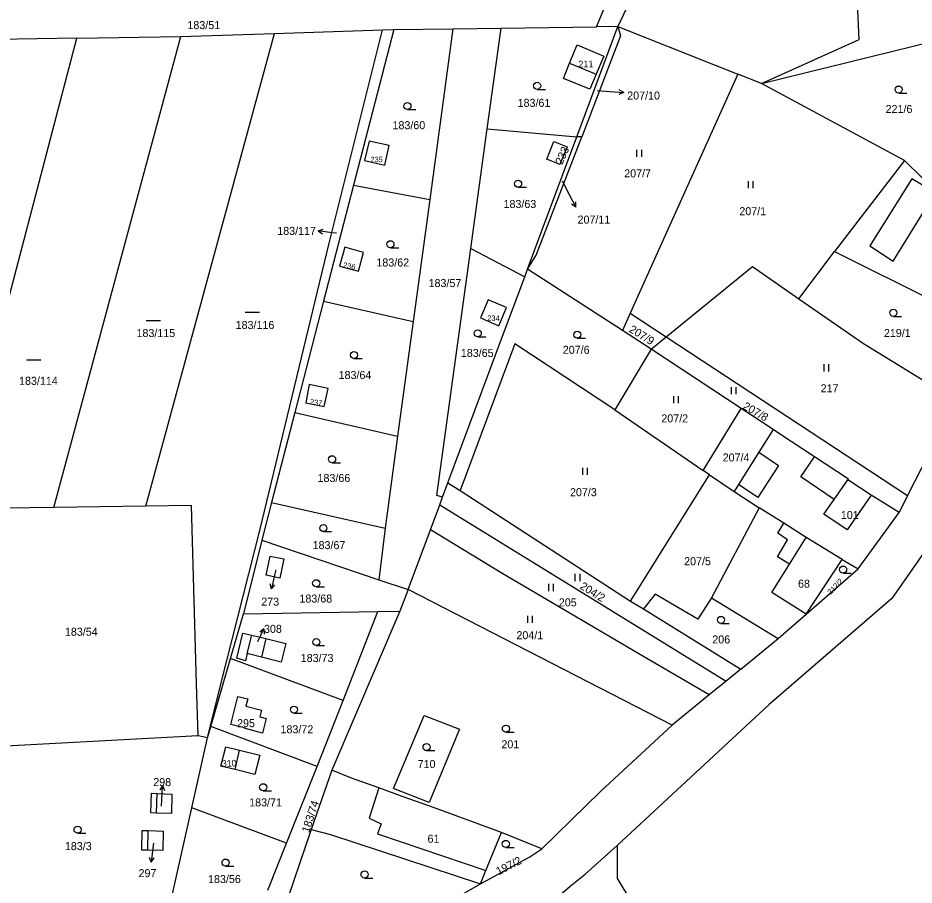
# Model space of a CAD drawing. Extents: x -747333 to -743907, y -1134120 to -1130051.
# Drawn here: x -746832.8 to -746642.5, y -1132263.2 to -1132079.1 of the extents above; entities that cross this region are included whole.
import ezdxf

# ---------------------------------------------------------------- set-up
doc = ezdxf.new("R2010")
doc.units = 0
for name, color, linetype in [('Hranice parcel', 7, 'Continuous'), ('Parcelní čísla', 7, 'Continuous'), ('Pop  PČ popisy', 7, 'Continuous'), ('Vnitřní kresba', 7, 'Continuous'), ('Značky kultur', 7, 'Continuous')]:
    doc.layers.add(name, color=color, linetype=linetype)

msp = doc.modelspace()

# ---------------------------------------------------------------- linework, layer by layer
at = {"layer": 'Hranice parcel'}
for p, q in [((-746778.25, -1132082.36), (-746755.32, -1132081.61)), ((-746752.93, -1132081.53), (-746761.49, -1132114.56)), ((-746755.32, -1132081.61), (-746752.93, -1132081.53)), ((-746752.93, -1132081.53), (-746740.4, -1132081.38)), ((-746740.4, -1132081.38), (-746745.32, -1132117.64)), ((-746740.4, -1132081.38), (-746730.14, -1132081.25)), ((-746733.1, -1132102.66), (-746730.14, -1132081.25)), ((-746730.14, -1132081.25), (-746709.89, -1132080.97)), ((-746714.1, -1132104.36), (-746705.38, -1132080.91)), ((-746705.38, -1132080.91), (-746709.89, -1132080.97)), ((-746705.38, -1132080.91), (-746679.89, -1132091)), ((-746705.38, -1132080.91), (-746704.8, -1132082.86)), ((-746820.24, -1132083.39), (-746845.06, -1132083.8)), ((-746825.13, -1132182.99), (-746798.2, -1132083.02)), ((-746820.24, -1132083.39), (-746798.2, -1132083.02)), ((-746805.63, -1132182.7), (-746778.25, -1132082.36)), ((-746798.2, -1132083.02), (-746778.25, -1132082.36)), ((-746704.8, -1132082.86), (-746713.07, -1132104.3)), ((-746674.91, -1132092.97), (-746635.72, -1132083.37)), ((-746679.89, -1132091), (-746702.74, -1132141.73)), ((-746674.91, -1132092.97), (-746679.89, -1132091)), ((-746644.51, -1132109.35), (-746674.91, -1132092.97)), ((-746736.6, -1132128.06), (-746733.1, -1132102.66)), ((-746733.1, -1132102.66), (-746714.1, -1132104.36)), ((-746724.55, -1132132.39), (-746714.1, -1132104.36)), ((-746713.07, -1132104.3), (-746714.1, -1132104.36)), ((-746644.51, -1132109.35), (-746659.43, -1132128.69)), ((-746640.76, -1132113.05), (-746644.51, -1132109.35)), ((-746761.49, -1132114.56), (-746767.86, -1132139.21)), ((-746761.49, -1132114.56), (-746745.32, -1132117.64)), ((-746745.32, -1132117.64), (-746748.85, -1132143.55)), ((-746743.8, -1132180.44), (-746736.6, -1132128.06)), ((-746736.6, -1132128.06), (-746725.17, -1132134.06)), ((-746666.94, -1132138.69), (-746659.43, -1132128.69)), ((-746659.43, -1132128.69), (-746625.72, -1132145.44)), ((-746725.17, -1132134.06), (-746724.55, -1132132.39)), ((-746704.42, -1132145.46), (-746724.55, -1132132.39)), ((-746767.86, -1132139.21), (-746773.98, -1132162.83)), ((-746767.86, -1132139.21), (-746748.85, -1132143.55)), ((-746702.74, -1132141.73), (-746704.42, -1132145.46)), ((-746702.74, -1132141.73), (-746695.1, -1132146.75)), ((-746748.85, -1132143.55), (-746752.17, -1132167.89)), ((-746698.35, -1132149.4), (-746704.42, -1132145.46)), ((-746698.35, -1132149.4), (-746695.1, -1132146.75)), ((-746695.1, -1132146.75), (-746643.87, -1132180.43)), ((-746698.35, -1132149.4), (-746706, -1132162.26)), ((-746679.2, -1132162.02), (-746698.35, -1132149.4)), ((-746633.63, -1132160.23), (-746643.87, -1132180.43)), ((-746773.98, -1132162.83), (-746778.93, -1132181.95)), ((-746773.98, -1132162.83), (-746752.17, -1132167.89)), ((-746706, -1132162.26), (-746687.28, -1132175.19)), ((-746687.28, -1132175.19), (-746679.2, -1132162.02)), ((-746672.44, -1132166.48), (-746679.2, -1132162.02)), ((-746752.17, -1132167.89), (-746754.82, -1132187.37)), ((-746685.93, -1132176.1), (-746687.28, -1132175.19)), ((-746702.69, -1132202.89), (-746685.93, -1132176.1)), ((-746685.93, -1132176.1), (-746680.69, -1132179.58)), ((-746742.61, -1132180.85), (-746741.45, -1132177.74)), ((-746741.45, -1132177.74), (-746738.86, -1132179.39)), ((-746742.61, -1132180.85), (-746743.8, -1132180.44)), ((-746743.19, -1132182.42), (-746742.61, -1132180.85)), ((-746738.86, -1132179.39), (-746702.69, -1132202.89)), ((-746680.69, -1132179.58), (-746675.38, -1132183.11)), ((-746643.87, -1132180.43), (-746645.7, -1132184.06)), ((-746805.63, -1132182.7), (-746825.13, -1132182.99)), ((-746778.93, -1132181.95), (-746781, -1132189.93)), ((-746778.93, -1132181.95), (-746754.82, -1132187.37)), ((-746745.18, -1132187.75), (-746743.19, -1132182.42)), ((-746743.19, -1132182.42), (-746682.41, -1132219.89)), ((-746675.38, -1132183.11), (-746685.49, -1132202.16)), ((-746654.39, -1132196.03), (-746645.7, -1132184.06)), ((-746754.82, -1132187.37), (-746756.13, -1132198.33)), ((-746749.91, -1132200.43), (-746745.18, -1132187.75)), ((-746781, -1132189.93), (-746784.83, -1132205.6)), ((-746781, -1132189.93), (-746756.13, -1132198.33)), ((-746665.44, -1132205.68), (-746657.77, -1132194.04)), ((-746657.77, -1132194.04), (-746654.39, -1132196.03)), ((-746665.44, -1132205.68), (-746654.39, -1132196.03)), ((-746756.13, -1132198.33), (-746749.91, -1132200.43)), ((-746749.91, -1132200.43), (-746751.65, -1132205.03)), ((-746693.83, -1132229.18), (-746749.91, -1132200.43)), ((-746702.69, -1132202.89), (-746699.96, -1132204.52)), ((-746685.49, -1132202.16), (-746671.39, -1132210.8)), ((-746787.59, -1132215.05), (-746784.83, -1132205.6)), ((-746784.83, -1132205.6), (-746756.31, -1132205.11)), ((-746751.65, -1132205.03), (-746766.12, -1132238.78)), ((-746763.69, -1132223.97), (-746756.31, -1132205.11)), ((-746756.31, -1132205.11), (-746751.65, -1132205.03)), ((-746699.96, -1132204.52), (-746679.29, -1132217.36)), ((-746671.39, -1132210.8), (-746665.44, -1132205.68)), ((-746679.29, -1132217.36), (-746671.39, -1132210.8)), ((-746791.83, -1132229.53), (-746787.59, -1132215.05)), ((-746763.69, -1132223.97), (-746787.59, -1132215.05)), ((-746679.29, -1132217.36), (-746682.41, -1132219.89)), ((-746682.41, -1132219.89), (-746686, -1132222.81)), ((-746769.22, -1132238.01), (-746763.69, -1132223.97)), ((-746686, -1132222.81), (-746693.83, -1132229.18)), ((-746792.52, -1132231.9), (-746791.83, -1132229.53)), ((-746769.22, -1132238.01), (-746791.83, -1132229.53)), ((-746795.83, -1132246.75), (-746792.52, -1132231.9)), ((-746792.52, -1132231.9), (-746794.52, -1132231.47)), ((-746775.72, -1132254.29), (-746769.22, -1132238.01)), ((-746766.12, -1132238.78), (-746770.48, -1132251.33)), ((-746801.64, -1132272.79), (-746795.83, -1132246.75)), ((-746775.72, -1132254.29), (-746795.83, -1132246.75)), ((-746721.51, -1132255.46), (-746730.11, -1132251.98)), ((-746779.69, -1132264.25), (-746775.72, -1132254.29)), ((-746739.61, -1132265.77), (-746734.54, -1132262.91))]:
    msp.add_line(p, q, dxfattribs=at)
for points in [[(-746709.89, -1132080.97), (-746700.88, -1132059.24), (-746690.31, -1132034.95), (-746646.39, -1131931.6)], [(-746640.16, -1131931.3), (-746678.35, -1132019.74), (-746690.91, -1132050.15), (-746705.38, -1132080.91)], [(-746674.91, -1132092.97), (-746654.17, -1132083.68), (-746655.72, -1132049.5), (-746655.89, -1132035.79), (-746596.68, -1131997.54)], [(-746792.52, -1132231.9), (-746789.57, -1132220.24), (-746781.38, -1132187.88), (-746766.7, -1132126.93), (-746755.32, -1132081.61)], [(-746858.02, -1132224.47), (-746835.83, -1132142.89), (-746820.24, -1132083.39)], [(-746711.32, -1132094.22), (-746716.94, -1132091.93), (-746715.63, -1132088.71), (-746714.06, -1132084.83), (-746708.4, -1132087.18), (-746709.98, -1132090.99), (-746711.32, -1132094.22)], [(-746724.55, -1132132.39), (-746722.76, -1132129.43), (-746713.07, -1132104.3)], [(-746753.94, -1132106.19), (-746758.21, -1132105.23), (-746759.16, -1132109.33), (-746754.88, -1132110.32), (-746753.94, -1132106.19)], [(-746718.96, -1132105.32), (-746716.14, -1132106.48), (-746717.68, -1132110.21), (-746720.5, -1132109.04), (-746718.96, -1132105.32)], [(-746764.45, -1132131.77), (-746760.45, -1132132.87), (-746759.36, -1132128.86), (-746763.36, -1132127.77), (-746764.45, -1132131.77)], [(-746695.1, -1132146.75), (-746676.81, -1132131.86), (-746666.94, -1132138.69)], [(-746741.45, -1132177.74), (-746729.85, -1132146.61), (-746725.17, -1132134.06)], [(-746732.9, -1132138.91), (-746734.55, -1132142.77), (-746730.68, -1132144.42), (-746729.03, -1132140.57), (-746732.9, -1132138.91)], [(-746666.94, -1132138.69), (-746653.23, -1132148.18), (-746633.63, -1132160.23)], [(-746706, -1132162.26), (-746727.28, -1132148.3), (-746738.86, -1132179.39)], [(-746770.91, -1132156.92), (-746771.66, -1132160.8), (-746767.74, -1132161.56), (-746766.92, -1132157.72), (-746770.91, -1132156.92)], [(-746672.44, -1132166.48), (-746675.45, -1132171.26), (-746679.79, -1132178.16), (-746680.69, -1132179.58)], [(-746645.7, -1132184.06), (-746651.6, -1132180.37), (-746656.53, -1132177.13), (-746656.42, -1132176.97), (-746663.67, -1132172.26), (-746671.09, -1132167.37), (-746672.44, -1132166.48)], [(-746627.53, -1132169.14), (-746637.59, -1132188.53), (-746647.21, -1132202.3), (-746673.25, -1132224.8), (-746705.52, -1132254.75)], [(-746794.52, -1132231.47), (-746794.83, -1132220.45), (-746795.89, -1132182.56), (-746805.63, -1132182.7)], [(-746825.13, -1132182.99), (-746845.75, -1132183.3), (-746844.91, -1132224.19)], [(-746657.77, -1132194.04), (-746665.4, -1132189.36), (-746670.13, -1132186.36), (-746675.38, -1132183.11)], [(-746686, -1132222.81), (-746700.07, -1132214.57), (-746729.82, -1132197.08), (-746745.18, -1132187.75)], [(-746779.23, -1132193.32), (-746776.31, -1132193.91), (-746777.12, -1132197.98), (-746780.05, -1132197.37), (-746779.23, -1132193.32)], [(-746685.49, -1132202.16), (-746688.44, -1132206.74), (-746697.45, -1132201.42), (-746699.96, -1132204.52)], [(-746783.07, -1132210.11), (-746780.12, -1132210.8), (-746775.87, -1132211.89), (-746776.88, -1132215.82), (-746781.07, -1132214.77), (-746784.07, -1132214.03), (-746784.43, -1132215.59), (-746786.31, -1132214.99), (-746785, -1132209.67), (-746783.07, -1132210.11)], [(-746794.52, -1132231.47), (-746844.62, -1132234.18), (-746844.91, -1132224.19)], [(-746780.82, -1132230.88), (-746784.71, -1132229.88), (-746784.68, -1132229.78), (-746787.58, -1132229.04), (-746786.06, -1132223.12), (-746783.97, -1132223.66), (-746784.36, -1132225.19), (-746781.01, -1132226.05), (-746781.38, -1132227.48), (-746780.03, -1132227.83), (-746780.82, -1132230.88)], [(-746746.53, -1132227.19), (-746739, -1132230.07), (-746745.42, -1132245.64), (-746753.02, -1132242.69), (-746746.53, -1132227.19)], [(-746721.51, -1132255.46), (-746709.03, -1132243.21), (-746693.83, -1132229.18)], [(-746785.69, -1132234.52), (-746781.4, -1132235.6), (-746782.44, -1132239.69), (-746786.66, -1132238.64), (-746789.66, -1132237.89), (-746788.62, -1132233.78), (-746785.69, -1132234.52)], [(-746730.11, -1132251.98), (-746744.54, -1132246.69), (-746750.97, -1132244.4), (-746756.12, -1132242.54), (-746761.95, -1132240.48), (-746766.12, -1132238.78)], [(-746803.22, -1132243.72), (-746800.06, -1132243.84), (-746800.18, -1132248), (-746803.33, -1132247.87), (-746804.5, -1132247.82), (-746804.37, -1132243.68), (-746803.22, -1132243.72)], [(-746801.92, -1132251.69), (-746801.99, -1132255.84), (-746805.19, -1132255.76), (-746806.42, -1132255.73), (-746806.38, -1132251.58), (-746805.12, -1132251.61), (-746801.92, -1132251.69)], [(-746770.48, -1132251.33), (-746776.66, -1132269.51), (-746771.04, -1132270.84)], [(-746770.48, -1132251.33), (-746766.36, -1132252.44), (-746734.54, -1132262.91)], [(-746734.54, -1132262.91), (-746733.4, -1132260.05), (-746730.11, -1132251.98)], [(-746733.81, -1132276.07), (-746730.72, -1132274.13), (-746718.09, -1132265.55), (-746715.48, -1132263.41), (-746712.32, -1132260.82), (-746705.52, -1132254.75)], [(-746705.52, -1132254.75), (-746705.52, -1132261.75), (-746702.56, -1132266.68), (-746651.51, -1132285.68), (-746635.38, -1132289.23)], [(-746734.54, -1132262.91), (-746724.11, -1132257.19), (-746721.51, -1132255.46)]]:
    msp.add_lwpolyline(points, dxfattribs=at)
at = {"layer": 'Pop  PČ popisy'}
for p, q in [((-746709.8, -1132094.52), (-746707.14, -1132094.71)), ((-746707.14, -1132094.71), (-746704.146, -1132094.919)), ((-746704.146, -1132094.919), (-746705.18, -1132095.349)), ((-746704.146, -1132094.919), (-746705.11, -1132094.35)), ((-746717.22, -1132113.7), (-746715.7, -1132116.6)), ((-746715.7, -1132116.6), (-746714.291, -1132119.25)), ((-746714.291, -1132119.25), (-746714.319, -1132118.13)), ((-746714.291, -1132119.25), (-746715.203, -1132118.601)), ((-746769.022, -1132124.262), (-746767.96, -1132123.906)), ((-746766.05, -1132124.68), (-746769.022, -1132124.262)), ((-746769.022, -1132124.262), (-746768.1, -1132124.898)), ((-746765.15, -1132124.8), (-746766.05, -1132124.68)), ((-746778.25, -1132197.36), (-746778.925, -1132200.284)), ((-746777.98, -1132196.22), (-746778.25, -1132197.36)), ((-746778.925, -1132200.284), (-746779.188, -1132199.196)), ((-746778.925, -1132200.284), (-746778.212, -1132199.421)), ((-746781.83, -1132211.46), (-746780.514, -1132208.763)), ((-746780.514, -1132208.763), (-746781.404, -1132209.443)), ((-746780.514, -1132208.763), (-746780.503, -1132209.882)), ((-746802.053, -1132242.043), (-746802.605, -1132243.017)), ((-746802.21, -1132245.04), (-746802.053, -1132242.043)), ((-746802.053, -1132242.043), (-746801.605, -1132243.069)), ((-746802.29, -1132246.38), (-746802.21, -1132245.04)), ((-746803.94, -1132254.29), (-746804.08, -1132255.35)), ((-746804.08, -1132255.35), (-746804.446, -1132258.329)), ((-746804.446, -1132258.329), (-746804.821, -1132257.274)), ((-746804.446, -1132258.329), (-746803.827, -1132257.396))]:
    msp.add_line(p, q, dxfattribs=at)
at = {"layer": 'Vnitřní kresba'}
for p, q in [((-746715.63, -1132088.71), (-746709.98, -1132090.99)), ((-746642.98, -1132113.24), (-746651.88, -1132127.45)), ((-746637.99, -1132116.23), (-746642.98, -1132113.24)), ((-746646.97, -1132130.75), (-746637.99, -1132116.23)), ((-746651.88, -1132127.45), (-746646.97, -1132130.75)), ((-746675.45, -1132171.26), (-746671.27, -1132174.11)), ((-746666.56, -1132176.49), (-746663.67, -1132172.26)), ((-746671.27, -1132174.11), (-746675.65, -1132180.87)), ((-746659.47, -1132181.31), (-746666.56, -1132176.49)), ((-746675.65, -1132180.87), (-746679.79, -1132178.16)), ((-746659.47, -1132181.31), (-746656.53, -1132177.13)), ((-746651.6, -1132180.37), (-746656.68, -1132187.78)), ((-746661.63, -1132184.39), (-746659.47, -1132181.31)), ((-746656.68, -1132187.78), (-746661.63, -1132184.39)), ((-746671.46, -1132188.47), (-746670.13, -1132186.36)), ((-746669.35, -1132189.9), (-746671.46, -1132188.47)), ((-746671.5, -1132193.47), (-746669.35, -1132189.9)), ((-746668.98, -1132195.04), (-746665.4, -1132189.36)), ((-746668.98, -1132195.04), (-746671.5, -1132193.47)), ((-746672.69, -1132201.07), (-746668.98, -1132195.04)), ((-746665.44, -1132205.68), (-746672.69, -1132201.07)), ((-746784.07, -1132214.03), (-746783.07, -1132210.11)), ((-746780.12, -1132210.8), (-746781.07, -1132214.77)), ((-746786.66, -1132238.64), (-746785.69, -1132234.52)), ((-746756.12, -1132242.54), (-746758.19, -1132248.97)), ((-746803.33, -1132247.87), (-746803.22, -1132243.72)), ((-746758.19, -1132248.97), (-746755.61, -1132250.15)), ((-746755.61, -1132250.15), (-746756.42, -1132252.29)), ((-746805.19, -1132255.76), (-746805.12, -1132251.61)), ((-746756.42, -1132252.29), (-746733.4, -1132260.05))]:
    msp.add_line(p, q, dxfattribs=at)
at = {"layer": 'Značky kultur'}
for p, q in [((-746722.523, -1132094.25), (-746720.773, -1132094.25)), ((-746645.773, -1132095.04), (-746644.023, -1132095.04)), ((-746750.053, -1132098.54), (-746748.303, -1132098.54)), ((-746701.331, -1132108.56), (-746701.331, -1132107.06)), ((-746700.33, -1132108.56), (-746700.33, -1132107.06)), ((-746677.681, -1132115.25), (-746677.681, -1132113.75)), ((-746676.68, -1132115.25), (-746676.68, -1132113.75)), ((-746726.563, -1132115.04), (-746724.813, -1132115.04)), ((-746753.663, -1132127.87), (-746751.913, -1132127.87)), ((-746784.498, -1132141.56), (-746781.498, -1132141.56)), ((-746646.903, -1132142.44), (-746645.153, -1132142.44)), ((-746805.518, -1132143.28), (-746802.518, -1132143.28)), ((-746735.133, -1132146.8), (-746733.383, -1132146.8)), ((-746713.993, -1132147.08), (-746712.243, -1132147.08)), ((-746830.918, -1132151.63), (-746827.918, -1132151.63)), ((-746761.413, -1132151.38), (-746759.663, -1132151.38)), ((-746661.581, -1132154.11), (-746661.581, -1132152.61)), ((-746660.58, -1132154.11), (-746660.58, -1132152.61)), ((-746681.271, -1132158.98), (-746681.271, -1132157.48)), ((-746680.27, -1132158.98), (-746680.27, -1132157.48)), ((-746693.521, -1132160.87), (-746693.521, -1132159.37)), ((-746692.52, -1132160.87), (-746692.52, -1132159.37)), ((-746766.053, -1132173.51), (-746764.303, -1132173.51)), ((-746712.831, -1132176.07), (-746712.831, -1132174.57)), ((-746711.83, -1132176.07), (-746711.83, -1132174.57)), ((-746767.903, -1132188.13), (-746766.153, -1132188.13)), ((-746714.421, -1132198.62), (-746714.421, -1132197.12)), ((-746713.42, -1132198.62), (-746713.42, -1132197.12)), ((-746657.573, -1132196.93), (-746655.823, -1132196.93)), ((-746769.433, -1132199.84), (-746767.683, -1132199.84)), ((-746720.061, -1132200.74), (-746720.061, -1132199.24)), ((-746719.06, -1132200.74), (-746719.06, -1132199.24)), ((-746724.481, -1132207.5), (-746724.481, -1132206)), ((-746723.48, -1132207.5), (-746723.48, -1132206)), ((-746683.493, -1132207.62), (-746681.743, -1132207.62)), ((-746769.403, -1132212.32), (-746767.653, -1132212.32)), ((-746774.143, -1132226.66), (-746772.393, -1132226.66)), ((-746729.163, -1132230.7), (-746727.413, -1132230.7)), ((-746746.003, -1132234.62), (-746744.253, -1132234.62)), ((-746780.683, -1132243.14), (-746778.933, -1132243.14)), ((-746820.093, -1132252.15), (-746818.343, -1132252.15)), ((-746729.173, -1132255.17), (-746727.423, -1132255.17)), ((-746788.673, -1132259.13), (-746786.923, -1132259.13)), ((-746759.163, -1132261.66), (-746757.413, -1132261.66))]:
    msp.add_line(p, q, dxfattribs=at)
for centre in [(-746722.523, -1132093.5), (-746645.773, -1132094.29), (-746750.053, -1132097.79), (-746726.563, -1132114.29), (-746753.663, -1132127.12), (-746646.903, -1132141.69), (-746735.133, -1132146.05), (-746713.993, -1132146.33), (-746761.413, -1132150.63), (-746766.053, -1132172.76), (-746767.903, -1132187.38), (-746657.573, -1132196.18), (-746769.433, -1132199.09), (-746683.493, -1132206.87), (-746769.403, -1132211.57), (-746774.143, -1132225.91), (-746729.163, -1132229.95), (-746746.003, -1132233.87), (-746780.683, -1132242.39), (-746820.093, -1132251.4), (-746729.173, -1132254.42), (-746788.673, -1132258.38), (-746759.163, -1132260.91)]:
    msp.add_circle(centre, 0.75, dxfattribs=at)

# ---------------------------------------------------------------- texts
at = {"layer": 'Parcelní čísla'}
for s, height, p in [('183/51', 1.7, (-746796.77, -1132081.46)), ('207/10', 1.7, (-746703.4, -1132096.406)), ('183/61', 1.7, (-746726.67, -1132097.96)), ('221/6', 1.7, (-746648.55, -1132099.27)), ('183/60', 1.7, (-746753.23, -1132102.71)), ('235', 1.14, (-746757.92, -1132109.7)), ('207/7', 1.7, (-746704.043, -1132112.93)), ('183/63', 1.7, (-746729.66, -1132119.43)), ('207/1', 1.7, (-746679.6, -1132120.96)), ('207/11', 1.7, (-746713.95, -1132122.743)), ('183/117', 1.7, (-746777.696, -1132125.14)), ('183/62', 1.7, (-746756.645, -1132131.85)), ('183/57', 1.7, (-746745.57, -1132136.22)), ('234', 1.14, (-746733.11, -1132143.39)), ('183/116', 1.7, (-746786.53, -1132145.11)), ('183/115', 1.7, (-746807.58, -1132146.83)), ('219/1', 1.7, (-746648.91, -1132146.82)), ('183/65', 1.7, (-746738.72, -1132151.05)), ('207/6', 1.7, (-746717.08, -1132150.39)), ('183/64', 1.7, (-746764.67, -1132155.74)), ('183/114', 1.7, (-746832.51, -1132156.97)), ('217', 1.7, (-746662.34, -1132158.55)), ('207/2', 1.7, (-746696.16, -1132164.94)), ('207/4', 1.7, (-746683.14, -1132173.24)), ('183/66', 1.7, (-746769.15, -1132177.6)), ('207/3', 1.7, (-746715.55, -1132180.61)), ('101', 1.7, (-746658.05, -1132185.45)), ('183/67', 1.7, (-746770.19, -1132191.85)), ('207/5', 1.7, (-746691.32, -1132195.26)), ('68', 1.7, (-746667.14, -1132200.03)), ('183/68', 1.7, (-746772.99, -1132203.19)), ('273', 1.7, (-746781.094, -1132203.843)), ('205', 1.7, (-746717.92, -1132204)), ('183/54', 1.7, (-746822.77, -1132210.23)), ('308', 1.7, (-746780.51, -1132209.62)), ('204/1', 1.7, (-746726.92, -1132210.97)), ('206', 1.7, (-746685.34, -1132211.87)), ('183/73', 1.7, (-746772.715, -1132215.8)), ('295', 1.7, (-746786.224, -1132229.64)), ('183/72', 1.7, (-746777.005, -1132230.94)), ('201', 1.7, (-746730.11, -1132234.13)), ('710', 1.7, (-746747.884, -1132238.32)), ('298', 1.7, (-746804.014, -1132242.15)), ('183/71', 1.7, (-746783.655, -1132246.46)), ('61', 1.7, (-746745.79, -1132254.17)), ('183/3', 1.7, (-746822.78, -1132255.74)), ('297', 1.7, (-746807.144, -1132261.48)), ('183/56', 1.7, (-746792.385, -1132262.73))]:
    msp.add_text(s, height=height, dxfattribs=at).set_placement(p)
for s, height, rotation, p in [('211', 1.436, 1, (-746713.755, -1132089.607)), ('233', 1.7, 66, (-746717.216, -1132110.359)), ('236', 1.14, 348, (-746763.808, -1132132.037)), ('207/9', 1.7, 328, (-746703.162, -1132145.611)), ('237', 1.14, 352, (-746770.829, -1132161.094)), ('207/8', 1.7, 330, (-746679.016, -1132161.969)), ('204/2', 1.7, 328, (-746713.59, -1132200.13)), ('212/2', 1.14, 46, (-746660.209, -1132201.575)), ('310', 1.386, 2, (-746789.434, -1132238.058)), ('183/74', 1.7, 72, (-746770.953, -1132252.186)), ('197/2', 1.7, 27, (-746730.714, -1132261.097))]:
    msp.add_text(s, height=height, rotation=rotation, dxfattribs=at).set_placement(p)

doc.saveas('drawing.dxf')
